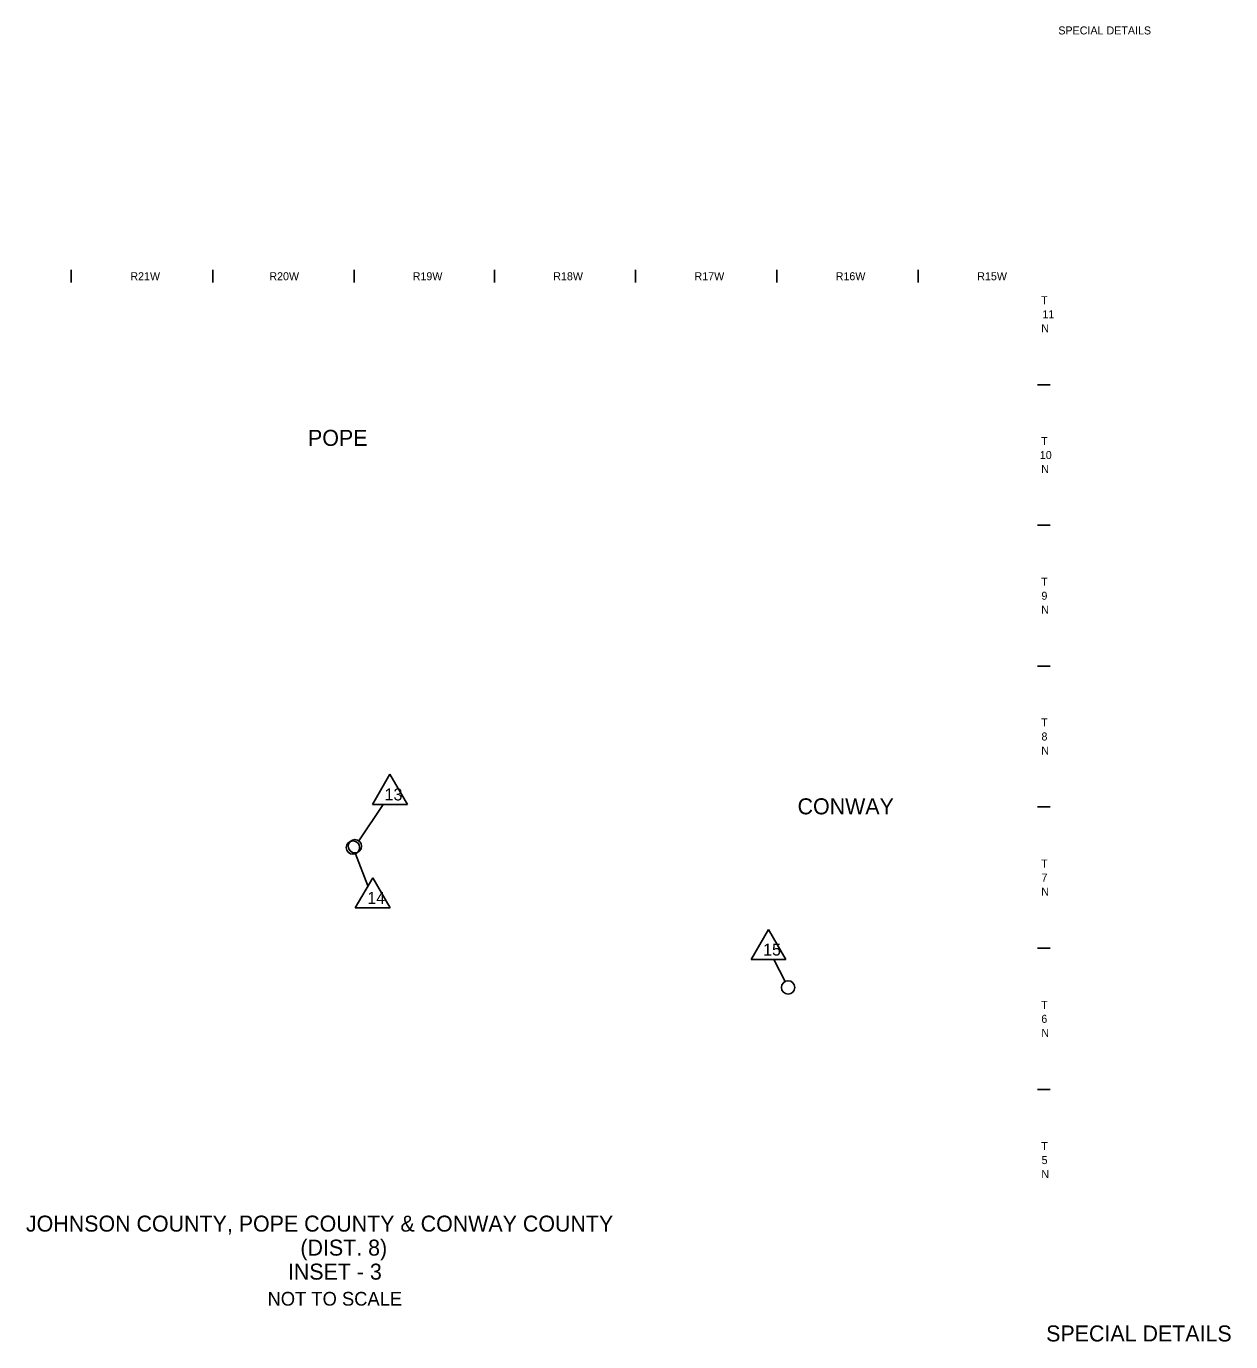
# Model space of a CAD drawing. Extents: x -17668 to 16999, y -17303 to 5867.
# Drawn here: x -11153 to -2121, y -17303 to -7443 of the extents above; entities that cross this region are included whole.
import ezdxf

# ---------------------------------------------------------------- set-up
doc = ezdxf.new("R2010")
doc.units = 0
for name, color, linetype in [('2', 7, 'Continuous'), ('42', 7, 'Continuous'), ('48', 7, 'Continuous'), ('Default', 7, 'Continuous')]:
    doc.layers.add(name, color=color, linetype=linetype)

msp = doc.modelspace()

# ---------------------------------------------------------------- linework, layer by layer
at = {"layer": '48'}
for p, q in [((-8426.3, -13049.6), (-8556.9, -13275.9)), ((-8295.7, -13275.9), (-8426.3, -13049.6)), ((-8660.7, -13547.1), (-8477.3, -13275.9)), ((-8556.9, -13275.9), (-8295.7, -13275.9)), ((-8590.9, -13885.7), (-8685.3, -13645.1)), ((-8555.6, -13824.7), (-8686.2, -14050.9)), ((-8425, -14050.9), (-8555.6, -13824.7)), ((-8686.2, -14050.9), (-8425, -14050.9)), ((-5587.3, -14212.3), (-5717.9, -14438.5)), ((-5456.7, -14438.5), (-5587.3, -14212.3)), ((-5717.9, -14438.5), (-5456.7, -14438.5)), ((-5463.4, -14602.9), (-5548.3, -14438.5))]:
    msp.add_line(p, q, dxfattribs=at)
for centre in [(-8703.6, -13598.5), (-8688.7, -13588.5), (-5440.4, -14647.3)]:
    msp.add_circle(centre, 50, dxfattribs=at)
at = {"layer": 'Default'}
for p, q in [((-10817.4, -9268.6), (-10817.4, -9363.6)), ((-9754, -9268.6), (-9754, -9363.6)), ((-8693.8, -9268.6), (-8693.8, -9363.6)), ((-7642.7, -9268.6), (-7642.7, -9363.6)), ((-6585.7, -9268.6), (-6585.7, -9363.6)), ((-5524, -9268.6), (-5524, -9363.6)), ((-4465.4, -9268.6), (-4465.4, -9363.6)), ((-3475.8, -10129.5), (-3570.8, -10129.5)), ((-3475.8, -11182.6), (-3570.8, -11182.6)), ((-3475.8, -12239.6), (-3570.8, -12239.6)), ((-3475.8, -13292.7), (-3570.8, -13292.7)), ((-3475.5, -14352.5), (-3570.5, -14352.5)), ((-3475.5, -15412.6), (-3570.5, -15412.6))]:
    msp.add_line(p, q, dxfattribs=at)

# ---------------------------------------------------------------- texts
at = {"layer": '2'}
for s, height, p in [('R21W', 60, (-10373.1, -9346.1)), ('R20W', 60, (-9330.7, -9346.1)), ('R19W', 60, (-8255.7, -9346.1)), ('R18W', 60, (-7201.6, -9346.1)), ('R17W', 60, (-6142.2, -9346.1)), ('R16W', 60, (-5083.5, -9346.1)), ('R15W', 60, (-4021.9, -9346.1)), ('T', 60, (-3542.9, -9526.1)), ('11', 60, (-3533.2, -9631.1)), ('N', 60, (-3542, -9736.1)), ('POPE', 120, (-9040.6, -10587.5)), ('T', 60, (-3542.9, -10581.1)), ('10', 60, (-3552.8, -10686.1)), ('N', 60, (-3542, -10791.1)), ('T', 60, (-3542.9, -11636.1)), ('9', 60, (-3540.6, -11741.1)), ('N', 60, (-3542, -11846.1)), ('T', 60, (-3542.9, -12691.1)), ('8', 60, (-3540.3, -12796.1)), ('N', 60, (-3542, -12901.1)), ('CONWAY', 120, (-5369.3, -13349.5)), ('T', 60, (-3542.9, -13748.9)), ('7', 60, (-3540.3, -13853.9)), ('N', 60, (-3542, -13958.9)), ('T', 60, (-3542.6, -14807.5)), ('6', 60, (-3541.6, -14912.5)), ('N', 60, (-3541.6, -15017.5)), ('T', 60, (-3542.2, -15866.2)), ('5', 60, (-3539.6, -15971.2)), ('N', 60, (-3541.2, -16076.2))]:
    msp.add_text(s, height=height, dxfattribs=at).set_placement(p)
at = {"layer": '42'}
msp.add_text('SPECIAL DETAILS', height=60, dxfattribs=at).set_placement((-3413.9, -7503.5))
at = {"layer": '48'}
for s, height, p in [('13', 90, (-8466.7, -13245.5)), ('14', 90, (-8596, -14020.5)), ('15', 90, (-5627.7, -14408.1)), ('JOHNSON COUNTY, POPE COUNTY & CONWAY COUNTY', 120, (-11155.9, -16477.4)), ('(DIST. 8)', 120, (-9097.9, -16657.4)), ('INSET - 3', 120, (-9191.5, -16837.4)), ('NOT TO SCALE', 102.885, (-9344.1, -17032.2)), ('SPECIAL DETAILS', 120, (-3505.1, -17300.8))]:
    msp.add_text(s, height=height, dxfattribs=at).set_placement(p)

doc.saveas('drawing.dxf')
